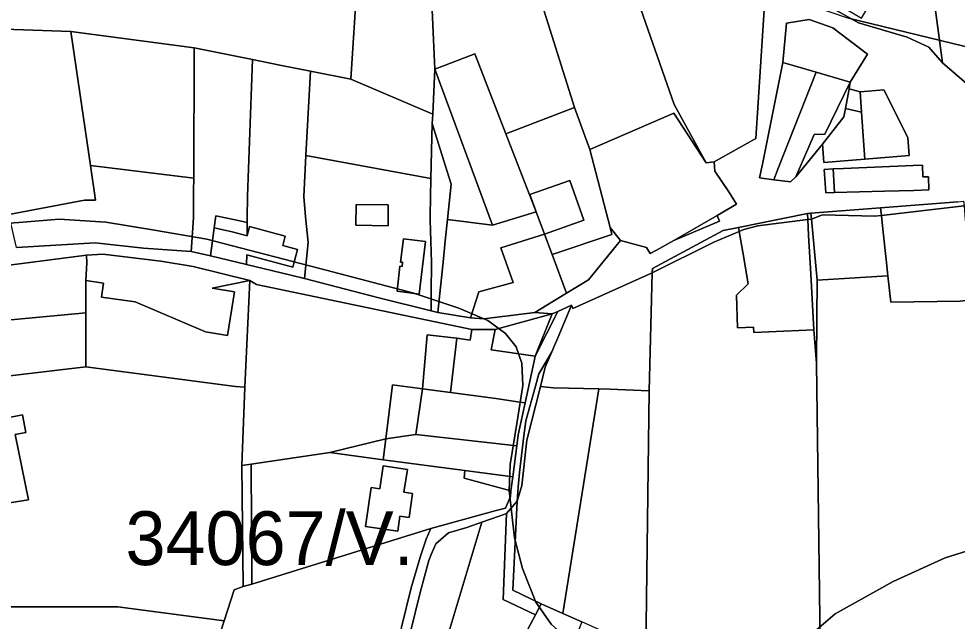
# Model space of a CAD drawing. Extents: x -535894 to -532827, y -1165802 to -1163635.
# Drawn here: x -534748.9 to -534487.4, y -1165239.1 to -1165071.2 of the extents above; entities that cross this region are included whole.
import ezdxf

# ---------------------------------------------------------------- set-up
doc = ezdxf.new("R2010")
doc.units = 0
for name, color, linetype in [('BPEJ_s', 7, 'Continuous'), ('orna_s', 7, 'Continuous'), ('ostatni_s', 7, 'Continuous'), ('sad_s', 7, 'Continuous'), ('trav_porost_s', 7, 'Continuous'), ('zahrada_s', 7, 'Continuous')]:
    doc.layers.add(name, color=color, linetype=linetype)

msp = doc.modelspace()

# ---------------------------------------------------------------- linework, layer by layer
at = {"layer": 'BPEJ_s'}
for points in [[(-534780.901, -1165003.39), (-534769.44, -1165004.02), (-534755.42, -1165007.85), (-534740.289, -1165015.17), (-534716.24, -1165028.71), (-534705.33, -1165033.01), (-534690.75, -1165036.2), (-534668.45, -1165039.7), (-534623.879, -1165046.695), (-534577.061, -1165054.045), (-534549.471, -1165060.17), (-534517.62, -1165071), (-534482.42, -1165079.6)], [(-534482.42, -1165079.6), (-534517.62, -1165071)], [(-534600.52, -1165239.92), (-534604.74, -1165233.86), (-534608.48, -1165224.47), (-534610.71, -1165215.87), (-534612.23, -1165202.72), (-534611.91, -1165195.48), (-534609.999, -1165183.45), (-534608.412, -1165173.45), (-534608.64, -1165167.21), (-534610.24, -1165162.67), (-534613.239, -1165158.905), (-534618.12, -1165155.34), (-534626.24, -1165151.91), (-534638.75, -1165147.69), (-534663.2, -1165141.32), (-534696.44, -1165132.66), (-534711.619, -1165130.09), (-534724.549, -1165127.901), (-534737.639, -1165127.111), (-534748.847, -1165127.956), (-534756.06, -1165128.5)], [(-534756.06, -1165128.5), (-534748.847, -1165127.956), (-534737.639, -1165127.111), (-534724.549, -1165127.901), (-534711.619, -1165130.09), (-534696.44, -1165132.66), (-534663.2, -1165141.32), (-534638.75, -1165147.69), (-534626.24, -1165151.91), (-534618.12, -1165155.34), (-534613.239, -1165158.905), (-534610.24, -1165162.67), (-534608.64, -1165167.21)], [(-534608.64, -1165167.21), (-534608.412, -1165173.45), (-534609.999, -1165183.45), (-534611.91, -1165195.48), (-534612.23, -1165202.72), (-534610.71, -1165215.87), (-534608.48, -1165224.47), (-534604.74, -1165233.86), (-534600.52, -1165239.92), (-534593.11, -1165246.69), (-534582.36, -1165253.77), (-534573.68, -1165257.329), (-534566.647, -1165258.95), (-534559.429, -1165258.95), (-534552.34, -1165257.6), (-534542.15, -1165253.22), (-534531.79, -1165246.05), (-534521.36, -1165237.13), (-534505.19, -1165228.05), (-534490.7, -1165221.44), (-534474.13, -1165216.26)], [(-534474.13, -1165216.26), (-534490.7, -1165221.44), (-534505.19, -1165228.05), (-534521.36, -1165237.13), (-534531.79, -1165246.05)]]:
    msp.add_lwpolyline(points, dxfattribs=at)
at = {"layer": 'orna_s'}
for points in [[(-534659.81, -1164981.95), (-534642.59, -1164987.17), (-534638.87, -1165010.05), (-534634.53, -1165050.1), (-534632.91, -1165085.29), (-534633.52, -1165097.84), (-534656.31, -1165088.09), (-534654.53, -1165060.65), (-534655.57, -1165032.56)], [(-534583.6, -1165131.32), (-534584.1, -1165129.38), (-534581.2, -1165132.99), (-534590.09, -1165143.97), (-534596.23, -1165147.7), (-534600.27, -1165136.91)], [(-534555.22, -1165133.48), (-534548.1, -1165130.49), (-534547.14, -1165136.27), (-534545.65, -1165145.14), (-534548.9, -1165148.28), (-534548.58, -1165157.34), (-534544.12, -1165157.18), (-534544.07, -1165158.63), (-534527.28, -1165157.93), (-534526.56, -1165167.24), (-534525.52, -1165245.33), (-534574.14, -1165247.28), (-534573.16, -1165174.91), (-534572.34, -1165142)], [(-534552.61, -1165130.25), (-534548.29, -1165129.37), (-534548.1, -1165130.49), (-534555.22, -1165133.48), (-534572.34, -1165142), (-534572.31, -1165140.81)], [(-534638.24, -1165187.11), (-534610.1, -1165190.23), (-534611.2, -1165198.9), (-534624.61, -1165197.13), (-534647.31, -1165194.16), (-534646.59, -1165188.32)], [(-534609.98, -1165205.7), (-534611.16, -1165230.48), (-534603.26, -1165234.27), (-534604.9, -1165237.35), (-534613.84, -1165233.07), (-534612.98, -1165209.1)], [(-534612.98, -1165209.1), (-534613.84, -1165233.07), (-534604.9, -1165237.35), (-534613.26, -1165253.08), (-534625.77, -1165251.25), (-534631.5, -1165250.59), (-534619.86, -1165211.52), (-534615.03, -1165209.82)], [(-534619.86, -1165211.52), (-534631.5, -1165250.59), (-534635.8, -1165250.1), (-534641.82, -1165249.4), (-534639.72, -1165242.1), (-534636.98, -1165231.14), (-534634.63, -1165222.23), (-534633.92, -1165220.53), (-534632.69, -1165217.6), (-534629.15, -1165214.48), (-534623.99, -1165212.98)]]:
    msp.add_lwpolyline(points, close=True, dxfattribs=at)
msp.add_lwpolyline([(-534654.53, -1165060.65), (-534656.31, -1165088.09), (-534667.56, -1165085.84), (-534676.08, -1165084.13), (-534683.71, -1165082.61), (-534700.02, -1165079.35), (-534734.34, -1165074.8), (-534763.47, -1165073.76)], dxfattribs=at)
at = {"layer": 'ostatni_s'}
for points in [[(-534466.76, -1165022.45), (-534488.01, -1165020.91), (-534500.56, -1165014.81), (-534508.03, -1165014.6), (-534515.85, -1165014.39), (-534517.16, -1165014.36), (-534529.63, -1165017.43), (-534533.96, -1165023.42), (-534534.04, -1165025.41), (-534537.78, -1165033.97), (-534538.58, -1165038), (-534540.03, -1165045.35), (-534538.55, -1165053.24), (-534536.12, -1165058.39), (-534533.08, -1165062.06), (-534523.11, -1165067.68), (-534514.83, -1165072.36), (-534501.27, -1165076.38), (-534495.29, -1165079.16), (-534491.48, -1165083.48), (-534478.11, -1165095.05)], [(-534487.16, -1165122.22), (-534508.71, -1165123.9), (-534528.11, -1165125.42), (-534529.13, -1165125.5), (-534548.29, -1165129.37), (-534552.61, -1165130.25), (-534572.31, -1165140.81), (-534572.34, -1165142), (-534594.43, -1165152.01), (-534594.86, -1165151.07), (-534598.63, -1165152.79), (-534600.19, -1165153.5), (-534605.04, -1165153.06), (-534596.23, -1165147.7), (-534590.09, -1165143.97), (-534581.2, -1165132.99), (-534573.9, -1165134.95), (-534572.91, -1165136.68), (-534571.13, -1165135.75), (-534566.36, -1165133), (-534553.63, -1165127.61), (-534554.3, -1165126.03), (-534548.88, -1165122.89), (-534551, -1165119.46), (-534554.9, -1165113.66), (-534555.08, -1165111.1), (-534543.46, -1165104.62), (-534540.87, -1165064.35)], [(-534749.51, -1165134.97), (-534727.56, -1165133.63), (-534714.12, -1165135.13), (-534700.81, -1165136.05), (-534695.46, -1165137.34), (-534685.39, -1165139.75), (-534673.06, -1165142.69), (-534669.22, -1165143.61), (-534655.64, -1165147.16), (-534648.54, -1165149.03), (-534633.92, -1165152.65), (-534632.07, -1165153.06), (-534623.03, -1165154.53), (-534619.23, -1165154.9), (-534608.06, -1165153.45), (-534605.04, -1165153.06), (-534600.19, -1165153.5), (-534616.15, -1165157.87), (-534622.58, -1165157.86), (-534682.61, -1165145.33), (-534684.51, -1165144.15), (-534700.3, -1165140.27), (-534709.27, -1165138.78), (-534725.42, -1165136.87), (-534729.95, -1165137.1), (-534754.46, -1165140.25)], [(-534642.21, -1165240.82), (-534639.56, -1165229.81), (-534636.93, -1165221.04), (-534635.35, -1165216.23), (-534634.06, -1165213.3), (-534615.85, -1165208.32), (-534613.23, -1165207.6), (-534611.88, -1165204.39), (-534611.73, -1165202.83), (-534611.2, -1165198.9), (-534610.1, -1165190.23), (-534609.72, -1165187.18), (-534607.79, -1165178.29), (-534605.25, -1165166.64), (-534604.96, -1165165.29), (-534598.63, -1165152.79), (-534594.86, -1165151.07), (-534598.66, -1165160.11), (-534599.6, -1165162.33), (-534600.32, -1165164.01), (-534601.37, -1165165.82), (-534603.9, -1165170.17), (-534604.88, -1165173.65), (-534607.6, -1165183.25), (-534608.15, -1165187.48), (-534609.36, -1165197.7), (-534609.68, -1165201.8), (-534609.98, -1165205.7), (-534612.98, -1165209.1), (-534615.03, -1165209.82), (-534619.86, -1165211.52), (-534623.99, -1165212.98), (-534629.15, -1165214.48), (-534632.69, -1165217.6), (-534633.92, -1165220.53), (-534634.63, -1165222.23), (-534636.98, -1165231.14), (-534639.72, -1165242.1)]]:
    msp.add_lwpolyline(points, dxfattribs=at)
for points in [[(-534528.58, -1165071.39), (-534534.97, -1165072.45), (-534535.98, -1165083.39), (-534541.67, -1165111.7), (-534542.44, -1165115.58), (-534538.48, -1165116.07), (-534533.82, -1165116.64), (-534532.37, -1165115.29), (-534524.95, -1165106.16), (-534524.55, -1165111.25), (-534513.11, -1165110.32), (-534500.76, -1165109.3), (-534501.16, -1165104.28), (-534507.77, -1165091), (-534514.4, -1165091.6), (-534517.52, -1165090.78), (-534517.17, -1165088.92), (-534512.37, -1165081.09), (-534522.06, -1165073.71)], [(-534528.58, -1165071.39), (-534522.06, -1165073.71), (-534512.37, -1165081.09), (-534517.17, -1165088.92), (-534526.65, -1165086.13), (-534535.98, -1165083.39), (-534534.97, -1165072.45)], [(-534514.4, -1165091.6), (-534514.01, -1165097.25), (-534518.52, -1165096.23), (-534517.52, -1165090.78)], [(-534514.4, -1165091.6), (-534507.77, -1165091), (-534501.16, -1165104.28), (-534500.76, -1165109.3), (-534513.11, -1165110.32), (-534513.46, -1165105.26), (-534514.01, -1165097.25)], [(-534589.74, -1165107.68), (-534566.34, -1165097.55), (-534557.29, -1165111.36), (-534555.08, -1165111.1), (-534554.9, -1165113.66), (-534551, -1165119.46), (-534548.88, -1165122.89), (-534554.3, -1165126.03), (-534566.36, -1165133), (-534571.13, -1165135.75), (-534572.91, -1165136.68), (-534573.9, -1165134.95), (-534581.2, -1165132.99), (-534584.1, -1165129.38)], [(-534518.52, -1165096.23), (-534514.01, -1165097.25), (-534513.46, -1165105.26), (-534513.11, -1165110.32), (-534524.55, -1165111.25), (-534524.95, -1165106.16), (-534518.94, -1165098.54)], [(-534630.5, -1165110.5), (-534628.41, -1165117.31), (-534629.43, -1165127.15), (-534630.05, -1165133.13), (-534630.54, -1165138.14), (-534632.07, -1165153.06), (-534633.92, -1165152.65), (-534633.9, -1165147.68), (-534633.88, -1165139.16), (-534634.19, -1165127.24), (-534634.22, -1165126.18), (-534634.01, -1165115.7), (-534633.69, -1165100.36)], [(-534634.01, -1165115.7), (-534634.22, -1165126.18), (-534634.19, -1165127.24), (-534633.88, -1165139.16), (-534633.9, -1165147.68), (-534633.92, -1165152.65), (-534648.54, -1165149.03), (-534655.64, -1165147.16), (-534669.22, -1165143.61), (-534668.22, -1165133.57), (-534668.93, -1165126.38), (-534669.47, -1165120.79), (-534668.84, -1165109.34)], [(-534728.88, -1165112.1), (-534700.11, -1165115.65), (-534700.12, -1165119.16), (-534700.15, -1165126.59), (-534700.73, -1165134.84), (-534700.81, -1165136.05), (-534714.12, -1165135.13), (-534727.56, -1165133.63), (-534749.51, -1165134.97), (-534751.61, -1165125.75), (-534730.52, -1165121.79), (-534727.46, -1165121.76)], [(-534499.64, -1165112.1), (-534519.03, -1165112.95), (-534521.96, -1165113.08), (-534524.4, -1165113.2), (-534523.98, -1165119.71), (-534521.53, -1165119.64), (-534507.64, -1165119.26), (-534499.45, -1165119.04), (-534495.25, -1165118.92), (-534495.36, -1165115.23), (-534496.95, -1165115.27), (-534497.04, -1165112.02)], [(-534521.96, -1165113.08), (-534521.53, -1165119.64), (-534523.98, -1165119.71), (-534524.4, -1165113.2)], [(-534499.64, -1165112.1), (-534497.04, -1165112.02), (-534496.95, -1165115.27), (-534495.36, -1165115.23), (-534495.25, -1165118.92), (-534499.45, -1165119.04), (-534507.64, -1165119.26), (-534521.53, -1165119.64), (-534521.96, -1165113.08), (-534519.03, -1165112.95)], [(-534595.34, -1165116.29), (-534591.44, -1165127.34), (-534602.37, -1165131.3), (-534604.71, -1165125.03), (-534606.42, -1165120.2)], [(-534654.84, -1165122.97), (-534654.9, -1165128.79), (-534645.96, -1165128.89), (-534645.89, -1165123.06)], [(-534654.84, -1165122.97), (-534645.89, -1165123.06), (-534645.96, -1165128.89), (-534654.9, -1165128.79)], [(-534485.59, -1165122.03), (-534485.47, -1165123.31), (-534508.47, -1165126.04), (-534508.71, -1165123.9), (-534487.16, -1165122.22)], [(-534508.47, -1165126.04), (-534485.47, -1165123.31), (-534485.11, -1165127.29), (-534482.54, -1165147.81), (-534482.37, -1165149.5), (-534486.55, -1165149.95), (-534505.88, -1165150.21), (-534506.66, -1165142.89), (-534507.16, -1165138.28), (-534508.07, -1165129.82)], [(-534688.56, -1165127.27), (-534685.22, -1165127.97), (-534685.25, -1165131.75), (-534689.38, -1165130.63), (-534694.4, -1165129.48), (-534693.94, -1165126.15)], [(-534604.71, -1165125.03), (-534602.37, -1165131.3), (-534614.5, -1165135.07), (-534611.13, -1165144.71), (-534620.7, -1165147.3), (-534623.03, -1165154.53), (-534632.07, -1165153.06), (-534630.54, -1165138.14), (-534630.05, -1165133.13), (-534629.43, -1165127.15), (-534616.82, -1165128.79)], [(-534554.3, -1165126.03), (-534553.63, -1165127.61), (-534566.36, -1165133)], [(-534529.03, -1165127.13), (-534542.89, -1165128.92), (-534546.81, -1165129.93), (-534548.1, -1165130.49), (-534548.29, -1165129.37), (-534529.13, -1165125.5)], [(-534694.4, -1165129.48), (-534689.38, -1165130.63), (-534685.25, -1165131.75), (-534684.55, -1165129.15), (-534674.61, -1165131.83), (-534675.31, -1165134.45), (-534671.16, -1165135.57), (-534672.46, -1165140.44), (-534685.34, -1165137.05), (-534685.39, -1165139.75), (-534695.46, -1165137.34)], [(-534542.89, -1165128.92), (-534529.03, -1165127.13), (-534528.78, -1165131.54), (-534528.17, -1165142.37), (-534527.28, -1165157.93), (-534544.07, -1165158.63), (-534544.12, -1165157.18), (-534548.58, -1165157.34), (-534548.9, -1165148.28), (-534545.65, -1165145.14), (-534547.14, -1165136.27), (-534548.1, -1165130.49), (-534546.81, -1165129.93)], [(-534641.67, -1165132.6), (-534642.47, -1165139.03), (-534641.89, -1165139.1), (-534642.02, -1165140.28), (-534642.63, -1165140.21), (-534643.4, -1165147.16), (-534637.3, -1165147.98), (-534635.55, -1165133.32)], [(-534641.67, -1165132.6), (-534635.55, -1165133.32), (-534637.3, -1165147.98), (-534643.4, -1165147.16), (-534642.63, -1165140.21), (-534642.02, -1165140.28), (-534641.89, -1165139.1), (-534642.47, -1165139.03)], [(-534729.95, -1165137.1), (-534729.88, -1165139.24), (-534730.19, -1165144.21), (-534730.17, -1165153.22), (-534757.12, -1165155.71), (-534764.6, -1165156.39), (-534774.56, -1165157.32), (-534774.83, -1165153.47), (-534775.05, -1165150.33), (-534775.25, -1165147.5), (-534775.49, -1165144.03), (-534773.4, -1165143.64), (-534754.46, -1165140.25)], [(-534725.42, -1165136.87), (-534709.27, -1165138.78), (-534700.3, -1165140.27), (-534684.51, -1165144.15), (-534694.96, -1165146.32), (-534688.78, -1165147.31), (-534690.66, -1165159.52), (-534696.83, -1165158.5), (-534716.45, -1165150.08), (-534725.77, -1165148.84), (-534725.23, -1165144.88), (-534730.19, -1165144.21), (-534729.88, -1165139.24), (-534729.95, -1165137.1)], [(-534572.34, -1165142), (-534573.16, -1165174.91), (-534584.13, -1165174.48), (-534587.22, -1165174.4), (-534599.92, -1165174.06), (-534603.51, -1165173.76), (-534602.14, -1165168.33), (-534600.32, -1165164.01), (-534599.6, -1165162.33), (-534598.66, -1165160.11), (-534594.86, -1165151.07), (-534594.43, -1165152.01)], [(-534598.63, -1165152.79), (-534604.96, -1165165.29), (-534600.19, -1165153.5)], [(-534616.15, -1165157.87), (-534600.19, -1165153.5), (-534604.96, -1165165.29), (-534617.24, -1165163.5)], [(-534622.58, -1165157.86), (-534616.15, -1165157.87), (-534617.24, -1165163.5), (-534604.96, -1165165.29), (-534605.25, -1165166.64), (-534607.79, -1165178.29), (-534609.24, -1165178.08), (-534615.95, -1165177.07), (-534628.59, -1165175.38), (-534626.83, -1165160.29), (-534623.09, -1165160.82)], [(-534601.37, -1165165.82), (-534600.32, -1165164.01), (-534602.14, -1165168.33), (-534603.51, -1165173.76), (-534607.25, -1165188.65), (-534608.72, -1165201.29), (-534609.98, -1165205.7), (-534609.68, -1165201.8), (-534609.36, -1165197.7), (-534608.15, -1165187.48), (-534607.6, -1165183.25), (-534604.88, -1165173.65), (-534603.9, -1165170.17)], [(-534636.37, -1165174.35), (-534628.59, -1165175.38), (-534615.95, -1165177.07), (-534609.24, -1165178.08), (-534607.79, -1165178.29), (-534609.72, -1165187.18), (-534610.1, -1165190.23), (-534638.24, -1165187.11)], [(-534747.79, -1165181.61), (-534746.85, -1165186.52), (-534749.82, -1165187.09), (-534746.16, -1165205.31), (-534765.68, -1165208.38), (-534774.55, -1165209.78), (-534775.06, -1165207.15), (-534787.13, -1165209.49), (-534788.65, -1165201.64), (-534789.14, -1165199.14), (-534790.92, -1165189.96), (-534779.72, -1165187.79), (-534772.09, -1165186.32)], [(-534686.67, -1165195.7), (-534684.12, -1165195.33), (-534683.94, -1165228.77), (-534686.31, -1165229.5)], [(-534640.55, -1165196.85), (-534641.54, -1165203.19), (-534639.12, -1165203.57), (-534640.07, -1165210.25), (-534642.63, -1165209.88), (-534643.25, -1165214.06), (-534652.28, -1165212.72), (-534650.63, -1165201.84), (-534648.22, -1165202.21), (-534647.3, -1165195.84)]]:
    msp.add_lwpolyline(points, close=True, dxfattribs=at)
at = {"layer": 'sad_s'}
for points in [[(-534526.42, -1165144.06), (-534506.66, -1165142.89), (-534505.88, -1165150.21), (-534486.55, -1165149.95), (-534482.37, -1165149.5), (-534479.49, -1165178.1), (-534474.69, -1165217.27), (-534470.72, -1165237.94), (-534490.64, -1165243.85), (-534498.4, -1165244.45), (-534504.24, -1165246.32), (-534515.07, -1165249.99), (-534525.69, -1165253.61), (-534525.52, -1165245.33), (-534526.56, -1165167.24), (-534526.49, -1165154.6)], [(-534773.45, -1165173.38), (-534730.12, -1165168.22), (-534689.23, -1165173.62), (-534688.37, -1165173.69), (-534685.89, -1165173.92), (-534686.67, -1165195.7), (-534686.31, -1165229.5), (-534688.84, -1165230.36), (-534691.61, -1165239), (-534721.27, -1165235.1), (-534761.05, -1165235.16), (-534760.2, -1165224.39), (-534765.68, -1165208.38), (-534746.16, -1165205.31), (-534749.82, -1165187.09), (-534746.85, -1165186.52), (-534747.79, -1165181.61), (-534772.09, -1165186.32)]]:
    msp.add_lwpolyline(points, close=True, dxfattribs=at)
at = {"layer": 'trav_porost_s'}
for points in [[(-534584.13, -1165044.84), (-534579.64, -1165056.67), (-534578.22, -1165060.77), (-534566.26, -1165095.11), (-534557.29, -1165111.36), (-534566.34, -1165097.55), (-534589.74, -1165107.68), (-534594.05, -1165095.99), (-534609.24, -1165047.46)], [(-534609.24, -1165047.46), (-534594.05, -1165095.99), (-534613.17, -1165103.24), (-534621.81, -1165080.98), (-534632.91, -1165085.29), (-534634.53, -1165050.1)], [(-534647.31, -1165194.16), (-534624.61, -1165197.13), (-534624.76, -1165199.3), (-534611.73, -1165202.83), (-534611.88, -1165204.39), (-534613.23, -1165207.6), (-534615.85, -1165208.32), (-534634.06, -1165213.3), (-534683.94, -1165228.77), (-534684.12, -1165195.33), (-534662.22, -1165192.14)], [(-534640.55, -1165196.85), (-534647.3, -1165195.84), (-534648.22, -1165202.21), (-534650.63, -1165201.84), (-534652.28, -1165212.72), (-534643.25, -1165214.06), (-534642.63, -1165209.88), (-534640.07, -1165210.25), (-534639.12, -1165203.57), (-534641.54, -1165203.19)], [(-534635.35, -1165216.23), (-534636.93, -1165221.04), (-534639.56, -1165229.81), (-534642.21, -1165240.82), (-534647.4, -1165260.65), (-534648.68, -1165264.17), (-534671.96, -1165259.81), (-534672.89, -1165264.71), (-534673.41, -1165267.52), (-534674.85, -1165275.19), (-534675.39, -1165278.09), (-534700.96, -1165268.14), (-534691.61, -1165239), (-534688.84, -1165230.36), (-534686.31, -1165229.5), (-534683.94, -1165228.77), (-534634.06, -1165213.3)]]:
    msp.add_lwpolyline(points, close=True, dxfattribs=at)
at = {"layer": 'zahrada_s'}
for points in [[(-534488.01, -1165020.91), (-534466.76, -1165022.45), (-534465.11, -1165045.38), (-534462.24, -1165085.02), (-534461.79, -1165091.28), (-534468.89, -1165092.92), (-534478.11, -1165095.05), (-534491.48, -1165083.48), (-534497.01, -1165041.71), (-534499.24, -1165024.85), (-534500.56, -1165014.81)], [(-534497.01, -1165041.71), (-534491.48, -1165083.48), (-534495.29, -1165079.16), (-534501.27, -1165076.38), (-534514.83, -1165072.36), (-534523.11, -1165067.68), (-534522.46, -1165066.03), (-534514.04, -1165071.03), (-534509.86, -1165063.98), (-534516.16, -1165060.24), (-534511.47, -1165040.97), (-534503.31, -1165041.78), (-534498.13, -1165041.73)], [(-534540.87, -1165064.35), (-534543.46, -1165104.62), (-534555.08, -1165111.1), (-534557.29, -1165111.36), (-534566.26, -1165095.11), (-534578.22, -1165060.77)], [(-534763.47, -1165073.76), (-534734.34, -1165074.8), (-534728.88, -1165112.1), (-534727.46, -1165121.76), (-534730.52, -1165121.79), (-534751.61, -1165125.75)], [(-534734.34, -1165074.8), (-534700.02, -1165079.35), (-534700.11, -1165115.65), (-534728.88, -1165112.1)], [(-534700.02, -1165079.35), (-534683.71, -1165082.61), (-534685.15, -1165120.7), (-534685.21, -1165126.74), (-534685.22, -1165127.97), (-534688.56, -1165127.27), (-534693.94, -1165126.15), (-534694.4, -1165129.48), (-534695.46, -1165137.34), (-534700.81, -1165136.05), (-534700.73, -1165134.84), (-534700.15, -1165126.59), (-534700.12, -1165119.16), (-534700.11, -1165115.65)], [(-534632.91, -1165085.29), (-534621.81, -1165080.98), (-534613.17, -1165103.24), (-534604.71, -1165125.03), (-534616.82, -1165128.79)], [(-534683.71, -1165082.61), (-534676.08, -1165084.13), (-534667.56, -1165085.84), (-534668.84, -1165109.34), (-534669.47, -1165120.79), (-534668.93, -1165126.38), (-534668.22, -1165133.57), (-534669.22, -1165143.61), (-534673.06, -1165142.69), (-534685.39, -1165139.75), (-534685.34, -1165137.05), (-534672.46, -1165140.44), (-534671.16, -1165135.57), (-534675.31, -1165134.45), (-534674.61, -1165131.83), (-534684.55, -1165129.15), (-534685.25, -1165131.75), (-534685.22, -1165127.97), (-534685.21, -1165126.74), (-534685.15, -1165120.7)], [(-534526.65, -1165086.13), (-534537.31, -1165113.11), (-534538.48, -1165116.07), (-534542.44, -1165115.58), (-534541.67, -1165111.7), (-534535.98, -1165083.39)], [(-534667.56, -1165085.84), (-534656.31, -1165088.09), (-534633.52, -1165097.84), (-534633.69, -1165100.36), (-534634.01, -1165115.7), (-534668.84, -1165109.34)], [(-534633.52, -1165097.84), (-534632.91, -1165085.29), (-534616.82, -1165128.79), (-534629.43, -1165127.15), (-534628.41, -1165117.31), (-534630.5, -1165110.5), (-534633.69, -1165100.36)], [(-534517.17, -1165088.92), (-534524.28, -1165103.39), (-534527.23, -1165103.5), (-534532.37, -1165115.29), (-534533.82, -1165116.64), (-534538.48, -1165116.07), (-534537.31, -1165113.11), (-534526.65, -1165086.13)], [(-534517.52, -1165090.78), (-534518.52, -1165096.23), (-534518.94, -1165098.54), (-534524.95, -1165106.16), (-534532.37, -1165115.29), (-534527.23, -1165103.5), (-534524.28, -1165103.39), (-534517.17, -1165088.92)], [(-534613.17, -1165103.24), (-534594.05, -1165095.99), (-534589.74, -1165107.68), (-534584.1, -1165129.38), (-534583.6, -1165131.32), (-534600.27, -1165136.91), (-534602.37, -1165131.3), (-534591.44, -1165127.34), (-534595.34, -1165116.29), (-534606.42, -1165120.2), (-534604.71, -1165125.03)], [(-534528.11, -1165125.42), (-534508.71, -1165123.9), (-534508.47, -1165126.04), (-534510.46, -1165126.27), (-534524.87, -1165125.86), (-534527.96, -1165127.06)], [(-534529.13, -1165125.5), (-534528.11, -1165125.42), (-534527.96, -1165127.06), (-534529.03, -1165127.13)], [(-534510.46, -1165126.27), (-534508.47, -1165126.04), (-534508.07, -1165129.82), (-534507.16, -1165138.28), (-534506.66, -1165142.89), (-534526.42, -1165144.06), (-534527.96, -1165127.06), (-534524.87, -1165125.86)], [(-534529.03, -1165127.13), (-534527.96, -1165127.06), (-534526.42, -1165144.06), (-534526.49, -1165154.6), (-534526.56, -1165167.24), (-534527.28, -1165157.93), (-534528.17, -1165142.37), (-534528.78, -1165131.54)], [(-534602.37, -1165131.3), (-534600.27, -1165136.91), (-534596.23, -1165147.7), (-534605.04, -1165153.06), (-534608.06, -1165153.45), (-534619.23, -1165154.9), (-534623.03, -1165154.53), (-534620.7, -1165147.3), (-534611.13, -1165144.71), (-534614.5, -1165135.07)], [(-534730.19, -1165144.21), (-534725.23, -1165144.88), (-534725.77, -1165148.84), (-534716.45, -1165150.08), (-534696.83, -1165158.5), (-534690.66, -1165159.52), (-534688.78, -1165147.31), (-534694.96, -1165146.32), (-534684.51, -1165144.15), (-534685.89, -1165173.92), (-534688.37, -1165173.69), (-534689.23, -1165173.62), (-534730.12, -1165168.22), (-534730.17, -1165153.22)], [(-534684.51, -1165144.15), (-534682.61, -1165145.33), (-534622.58, -1165157.86), (-534623.09, -1165160.82), (-534626.83, -1165160.29), (-534635.03, -1165159.35), (-534636.37, -1165174.35), (-534644.72, -1165173.23), (-534646.59, -1165188.32), (-534662.22, -1165192.14), (-534684.12, -1165195.33), (-534686.67, -1165195.7), (-534685.89, -1165173.92)], [(-534730.17, -1165153.22), (-534730.12, -1165168.22), (-534773.45, -1165173.38), (-534774.56, -1165157.32), (-534764.6, -1165156.39), (-534764.14, -1165161.37), (-534756.67, -1165160.69), (-534757.12, -1165155.71)], [(-534635.03, -1165159.35), (-534626.83, -1165160.29), (-534628.59, -1165175.38), (-534636.37, -1165174.35)], [(-534644.72, -1165173.23), (-534636.37, -1165174.35), (-534638.24, -1165187.11), (-534646.59, -1165188.32)], [(-534599.92, -1165174.06), (-534587.22, -1165174.4), (-534597.25, -1165236.95), (-534603.26, -1165234.27), (-534611.16, -1165230.48), (-534609.98, -1165205.7), (-534608.72, -1165201.29), (-534607.25, -1165188.65), (-534603.51, -1165173.76)], [(-534587.22, -1165174.4), (-534584.13, -1165174.48), (-534573.16, -1165174.91), (-534574.14, -1165247.28), (-534591.99, -1165239.3), (-534597.25, -1165236.95)], [(-534662.22, -1165192.14), (-534646.59, -1165188.32), (-534647.31, -1165194.16)], [(-534611.2, -1165198.9), (-534611.73, -1165202.83), (-534624.76, -1165199.3), (-534624.61, -1165197.13)], [(-534761.05, -1165235.16), (-534721.27, -1165235.1), (-534691.61, -1165239), (-534700.96, -1165268.14), (-534719.29, -1165264.53), (-534730.57, -1165265.33), (-534763.18, -1165261.89)], [(-534603.26, -1165234.27), (-534597.25, -1165236.95), (-534591.99, -1165239.3), (-534623.17, -1165318.51), (-534633.83, -1165316.18), (-534637.1, -1165315.06), (-534627.97, -1165285.63), (-534627.83, -1165285.22), (-534624.62, -1165276.23), (-534613.26, -1165253.08), (-534604.9, -1165237.35)]]:
    msp.add_lwpolyline(points, close=True, dxfattribs=at)

# ---------------------------------------------------------------- texts
at = {"layer": 'BPEJ_s'}
msp.add_text('34067/V.', height=15, dxfattribs=at).set_placement((-534719.114, -1165223.504))

doc.saveas('drawing.dxf')
